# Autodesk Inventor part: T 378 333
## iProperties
Company: Mayer & Müller AG Schaltgeräte
Created: 2006-10
Part Number: T 378 333
Material: Hm34/ME730
Document SubType Name: Modeling
Designer: I.Baliuc
Manufacturer: Standard
Standards Organization: Custom
Description: Isolierhülse
Density: 0.94 g/cm^3
HalbzeugNorm: EN 60893
Zweck: für Spulenbefestigung
Abmessung: Ø16 - 12,5
Author: T.Messerschmitt
Revision Number: 378333
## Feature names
1. Drehung1 [Revolution]
